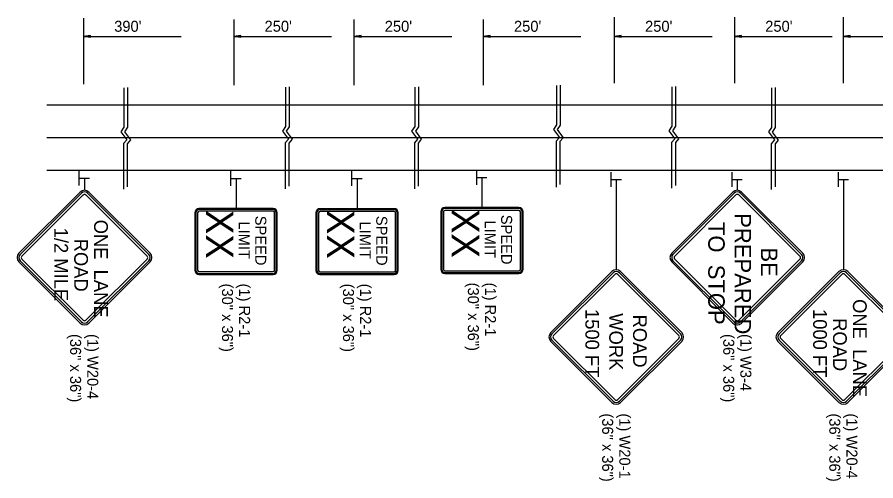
# Model space of a CAD drawing. Extents: x 1930579 to 1939784, y 596179 to 597522.
# Drawn here: x 1937482.9 to 1937952, y 596736 to 596989.5 of the extents above; entities that cross this region are included whole.
import ezdxf

# ---------------------------------------------------------------- set-up
doc = ezdxf.new("R2010")
doc.units = 0
for name, color, linetype in [('Default', 7, 'Continuous'), ('P_TC_Signs_Permanent', 7, 'Continuous'), ('P_TC_Signs_Temporary', 7, 'Continuous'), ('R_Annotation', 7, 'Continuous')]:
    doc.layers.add(name, color=color, linetype=linetype)

msp = doc.modelspace()

# ---------------------------------------------------------------- linework, layer by layer
at = {"layer": 'Default'}
for p, q in [((1937519.07, 596988.93), (1937519.07, 596952.91)), ((1937519.11, 596988.91), (1937519.11, 596952.89)), ((1937601.26, 596988.25), (1937601.26, 596952.22)), ((1937666.91, 596988.25), (1937666.91, 596952.22)), ((1937737.52, 596988.25), (1937737.52, 596952.22)), ((1937809.11, 596989.48), (1937809.11, 596953.45)), ((1937874.77, 596989.48), (1937874.77, 596953.45)), ((1937934.22, 596989.48), (1937934.22, 596953.45)), ((1937522.91, 596979.49), (1937519.07, 596978.92)), ((1937522.91, 596978.34), (1937519.07, 596978.92)), ((1937522.95, 596979.47), (1937519.11, 596978.9)), ((1937522.95, 596978.32), (1937519.11, 596978.9)), ((1937519.11, 596978.9), (1937572.51, 596978.9)), ((1937522.91, 596979.4), (1937519.71, 596978.92)), ((1937522.91, 596978.44), (1937519.71, 596978.92)), ((1937522.95, 596979.38), (1937519.75, 596978.9)), ((1937522.95, 596978.42), (1937519.75, 596978.9)), ((1937522.91, 596979.3), (1937520.37, 596978.92)), ((1937522.91, 596978.53), (1937520.37, 596978.92)), ((1937522.95, 596979.28), (1937520.41, 596978.9)), ((1937522.95, 596978.51), (1937520.41, 596978.9)), ((1937522.91, 596979.2), (1937521.01, 596978.92)), ((1937522.91, 596978.63), (1937521.01, 596978.92)), ((1937522.95, 596979.18), (1937521.05, 596978.9)), ((1937522.95, 596978.61), (1937521.05, 596978.9)), ((1937522.91, 596979.1), (1937521.66, 596978.92)), ((1937522.91, 596978.73), (1937521.66, 596978.92)), ((1937522.95, 596979.08), (1937521.7, 596978.9)), ((1937522.95, 596978.71), (1937521.7, 596978.9)), ((1937522.91, 596979.01), (1937522.3, 596978.92)), ((1937522.91, 596978.83), (1937522.3, 596978.92)), ((1937522.95, 596978.99), (1937522.34, 596978.9)), ((1937522.95, 596978.81), (1937522.34, 596978.9)), ((1937522.91, 596978.34), (1937522.91, 596979.49)), ((1937522.95, 596978.32), (1937522.95, 596979.47)), ((1937605.1, 596979.49), (1937601.26, 596978.92)), ((1937601.26, 596978.92), (1937654.66, 596978.92)), ((1937605.1, 596978.34), (1937601.26, 596978.92)), ((1937605.1, 596979.4), (1937601.9, 596978.92)), ((1937605.1, 596978.44), (1937601.9, 596978.92)), ((1937605.1, 596979.3), (1937602.56, 596978.92)), ((1937605.1, 596978.53), (1937602.56, 596978.92)), ((1937605.1, 596979.2), (1937603.2, 596978.92)), ((1937605.1, 596978.63), (1937603.2, 596978.92)), ((1937605.1, 596979.1), (1937603.85, 596978.92)), ((1937605.1, 596978.73), (1937603.85, 596978.92)), ((1937605.1, 596979.01), (1937604.49, 596978.92)), ((1937605.1, 596978.83), (1937604.49, 596978.92)), ((1937605.1, 596978.34), (1937605.1, 596979.49)), ((1937670.75, 596979.49), (1937666.91, 596978.92)), ((1937666.91, 596978.92), (1937720.31, 596978.92)), ((1937670.75, 596978.34), (1937666.91, 596978.92)), ((1937670.75, 596979.4), (1937667.55, 596978.92)), ((1937670.75, 596978.44), (1937667.55, 596978.92)), ((1937670.75, 596979.3), (1937668.21, 596978.92)), ((1937670.75, 596978.53), (1937668.21, 596978.92)), ((1937670.75, 596979.2), (1937668.85, 596978.92)), ((1937670.75, 596978.63), (1937668.85, 596978.92)), ((1937670.75, 596979.1), (1937669.5, 596978.92)), ((1937670.75, 596978.73), (1937669.5, 596978.92)), ((1937670.75, 596979.01), (1937670.14, 596978.92)), ((1937670.75, 596978.83), (1937670.14, 596978.92)), ((1937670.75, 596978.34), (1937670.75, 596979.49)), ((1937741.36, 596979.49), (1937737.52, 596978.92)), ((1937737.52, 596978.92), (1937790.92, 596978.92)), ((1937741.36, 596978.34), (1937737.52, 596978.92)), ((1937741.36, 596979.4), (1937738.16, 596978.92)), ((1937741.36, 596978.44), (1937738.16, 596978.92)), ((1937741.36, 596979.3), (1937738.82, 596978.92)), ((1937741.36, 596978.53), (1937738.82, 596978.92)), ((1937741.36, 596979.2), (1937739.46, 596978.92)), ((1937741.36, 596978.63), (1937739.46, 596978.92)), ((1937741.36, 596979.1), (1937740.11, 596978.92)), ((1937741.36, 596978.73), (1937740.11, 596978.92)), ((1937741.36, 596979.01), (1937740.75, 596978.92)), ((1937741.36, 596978.83), (1937740.75, 596978.92)), ((1937741.36, 596978.34), (1937741.36, 596979.49)), ((1937812.95, 596979.49), (1937809.11, 596978.92)), ((1937809.11, 596978.92), (1937862.52, 596978.92)), ((1937812.95, 596978.34), (1937809.11, 596978.92)), ((1937812.95, 596979.4), (1937809.76, 596978.92)), ((1937812.95, 596978.44), (1937809.76, 596978.92)), ((1937812.95, 596979.3), (1937810.42, 596978.92)), ((1937812.95, 596978.53), (1937810.42, 596978.92)), ((1937812.95, 596979.2), (1937811.05, 596978.92)), ((1937812.95, 596978.63), (1937811.05, 596978.92)), ((1937812.95, 596979.1), (1937811.7, 596978.92)), ((1937812.95, 596978.73), (1937811.7, 596978.92)), ((1937812.95, 596979.01), (1937812.35, 596978.92)), ((1937812.95, 596978.83), (1937812.35, 596978.92)), ((1937812.95, 596978.34), (1937812.95, 596979.49)), ((1937878.6, 596979.49), (1937874.77, 596978.92)), ((1937874.77, 596978.92), (1937928.17, 596978.92)), ((1937878.6, 596978.34), (1937874.77, 596978.92)), ((1937878.6, 596979.4), (1937875.41, 596978.92)), ((1937878.6, 596978.44), (1937875.41, 596978.92)), ((1937878.6, 596979.3), (1937876.07, 596978.92)), ((1937878.6, 596978.53), (1937876.07, 596978.92)), ((1937878.6, 596979.2), (1937876.71, 596978.92)), ((1937878.6, 596978.63), (1937876.71, 596978.92)), ((1937878.6, 596979.1), (1937877.36, 596978.92)), ((1937878.6, 596978.73), (1937877.36, 596978.92)), ((1937878.6, 596979.01), (1937878, 596978.92)), ((1937878.6, 596978.83), (1937878, 596978.92)), ((1937878.6, 596978.34), (1937878.6, 596979.49)), ((1937938.06, 596979.49), (1937934.22, 596978.92)), ((1937934.22, 596978.92), (1938033.98, 596978.92)), ((1937938.06, 596978.34), (1937934.22, 596978.92)), ((1937938.06, 596979.4), (1937934.86, 596978.92)), ((1937938.06, 596978.44), (1937934.86, 596978.92)), ((1937938.06, 596979.3), (1937935.52, 596978.92)), ((1937938.06, 596978.53), (1937935.52, 596978.92)), ((1937938.06, 596979.2), (1937936.16, 596978.92)), ((1937938.06, 596978.63), (1937936.16, 596978.92)), ((1937938.06, 596979.1), (1937936.81, 596978.92)), ((1937938.06, 596978.73), (1937936.81, 596978.92)), ((1937938.06, 596979.01), (1937937.45, 596978.92)), ((1937938.06, 596978.83), (1937937.45, 596978.92)), ((1937938.06, 596978.34), (1937938.06, 596979.49)), ((1937499.1, 596941.48), (1937601.26, 596941.48)), ((1937601.26, 596941.48), (1938703.26, 596941.48)), ((1937499.1, 596923.69), (1938703.26, 596923.69)), ((1937499.1, 596905.9), (1937601.26, 596905.9)), ((1937516.85, 596897.44), (1937516.85, 596905.45)), ((1937599.64, 596897.28), (1937599.64, 596905.28)), ((1937601.26, 596905.9), (1938703.26, 596905.9)), ((1937665.73, 596897.22), (1937665.73, 596905.22)), ((1937733.95, 596897.8), (1937733.95, 596905.8)), ((1937807.49, 596896.77), (1937807.49, 596904.77)), ((1937873.46, 596896.77), (1937873.46, 596904.77)), ((1937931.57, 596896.77), (1937931.57, 596904.77)), ((1937516.97, 596901.42), (1937522.43, 596901.42)), ((1937599.75, 596901.26), (1937605.22, 596901.26)), ((1937665.85, 596901.2), (1937671.32, 596901.2)), ((1937734.07, 596901.78), (1937739.54, 596901.78)), ((1937807.61, 596900.75), (1937813.07, 596900.75)), ((1937873.57, 596900.75), (1937879.04, 596900.75)), ((1937931.69, 596900.75), (1937937.15, 596900.75))]:
    msp.add_line(p, q, dxfattribs=at)
for points in [[(1937541.15, 596950.86), (1937541.15, 596929.33), (1937539.49, 596926.86), (1937542.73, 596922.43), (1937541.02, 596920.39), (1937541.02, 596895.36)], [(1937543.19, 596951.05), (1937543.19, 596929.25), (1937541.53, 596926.78), (1937544.77, 596922.35), (1937543.07, 596920.3), (1937543.06, 596896.8)], [(1937629.47, 596951.2), (1937629.47, 596929.67), (1937627.81, 596927.2), (1937631.05, 596922.77), (1937629.35, 596920.73), (1937629.34, 596895.7)], [(1937631.52, 596951.39), (1937631.52, 596929.59), (1937629.86, 596927.12), (1937633.09, 596922.69), (1937631.39, 596920.64), (1937631.39, 596897.14)], [(1937700.08, 596951.2), (1937700.08, 596929.67), (1937698.42, 596927.2), (1937701.66, 596922.77), (1937699.96, 596920.73), (1937699.95, 596895.7)], [(1937702.13, 596951.39), (1937702.13, 596929.59), (1937700.47, 596927.12), (1937703.7, 596922.69), (1937702, 596920.64), (1937702, 596897.14)], [(1937777.52, 596952.08), (1937777.52, 596930.56), (1937775.86, 596928.09), (1937779.1, 596923.66), (1937777.4, 596921.61), (1937777.39, 596896.59)], [(1937779.57, 596952.28), (1937779.57, 596930.47), (1937777.91, 596928), (1937781.14, 596923.57), (1937779.44, 596921.53), (1937779.44, 596898.03)], [(1937840.57, 596951.41), (1937840.57, 596929.89), (1937838.9, 596927.42), (1937842.14, 596922.99), (1937840.44, 596920.94), (1937840.43, 596895.92)], [(1937842.61, 596951.61), (1937842.61, 596929.8), (1937840.95, 596927.33), (1937844.19, 596922.9), (1937842.48, 596920.86), (1937842.48, 596897.36)], [(1937895.03, 596950.77), (1937895.03, 596929.24), (1937893.37, 596926.77), (1937896.6, 596922.34), (1937894.9, 596920.3), (1937894.89, 596895.27)], [(1937897.07, 596950.96), (1937897.07, 596929.16), (1937895.41, 596926.69), (1937898.65, 596922.26), (1937896.94, 596920.21), (1937896.94, 596896.71)]]:
    msp.add_lwpolyline(points, dxfattribs=at)
at = {"layer": 'P_TC_Signs_Permanent'}
for p, q in [((1937873.92, 596893.84), (1937840.51, 596860.43)), ((1937874.58, 596893.18), (1937841.17, 596859.77)), ((1937875.51, 596892.25), (1937842.1, 596858.84)), ((1937910.51, 596858.84), (1937877.1, 596892.25)), ((1937911.44, 596859.77), (1937878.03, 596893.18)), ((1937912.1, 596860.43), (1937878.69, 596893.84)), ((1937622.74, 596884.83), (1937582.24, 596884.83)), ((1937688.83, 596884.77), (1937648.33, 596884.77)), ((1937757.05, 596885.35), (1937716.55, 596885.35)), ((1937757.05, 596884.79), (1937716.55, 596884.79)), ((1937579.99, 596882.58), (1937579.99, 596851.08)), ((1937580.55, 596882.58), (1937580.55, 596851.08)), ((1937581.49, 596882.58), (1937581.49, 596851.08)), ((1937622.74, 596884.27), (1937582.24, 596884.27)), ((1937622.74, 596883.33), (1937582.24, 596883.33)), ((1937623.49, 596851.08), (1937623.49, 596882.58)), ((1937624.42, 596851.08), (1937624.42, 596882.58)), ((1937624.99, 596851.08), (1937624.99, 596882.58)), ((1937646.08, 596882.52), (1937646.08, 596851.02)), ((1937646.65, 596882.52), (1937646.65, 596851.02)), ((1937647.58, 596882.52), (1937647.58, 596851.02)), ((1937688.83, 596884.21), (1937648.33, 596884.21)), ((1937688.83, 596883.27), (1937648.33, 596883.27)), ((1937689.58, 596851.02), (1937689.58, 596882.52)), ((1937690.52, 596851.02), (1937690.52, 596882.52)), ((1937691.08, 596851.02), (1937691.08, 596882.52)), ((1937714.3, 596883.1), (1937714.3, 596851.6)), ((1937714.87, 596883.1), (1937714.87, 596851.6)), ((1937715.8, 596883.1), (1937715.8, 596851.6)), ((1937757.05, 596883.85), (1937716.55, 596883.85)), ((1937757.8, 596851.6), (1937757.8, 596883.1)), ((1937758.74, 596851.6), (1937758.74, 596883.1)), ((1937759.3, 596851.6), (1937759.3, 596883.1)), ((1937842.1, 596857.25), (1937875.51, 596823.84)), ((1937877.1, 596823.84), (1937910.51, 596857.25)), ((1937840.51, 596855.66), (1937873.92, 596822.25)), ((1937841.17, 596856.32), (1937874.58, 596822.91)), ((1937878.03, 596822.91), (1937911.44, 596856.32)), ((1937878.69, 596822.25), (1937912.1, 596855.66)), ((1937582.24, 596850.33), (1937622.74, 596850.33)), ((1937582.24, 596849.39), (1937622.74, 596849.39)), ((1937582.24, 596848.83), (1937622.74, 596848.83)), ((1937648.33, 596850.27), (1937688.83, 596850.27)), ((1937648.33, 596849.34), (1937688.83, 596849.34)), ((1937648.33, 596848.77), (1937688.83, 596848.77)), ((1937716.55, 596850.85), (1937757.05, 596850.85)), ((1937716.55, 596849.91), (1937757.05, 596849.91)), ((1937716.55, 596849.35), (1937757.05, 596849.35))]:
    msp.add_line(p, q, dxfattribs=at)
for centre, radius, start, end in [((1937876.31, 596891.45), 3.38, 45, 135), ((1937876.31, 596891.45), 2.44, 45, 135), ((1937876.31, 596891.45), 1.13, 45, 135), ((1937582.24, 596882.58), 2.25, 90, 180), ((1937622.74, 596882.58), 2.25, 360, 90), ((1937648.33, 596882.52), 2.25, 90, 180), ((1937688.83, 596882.52), 2.25, 360, 90), ((1937716.55, 596883.1), 2.25, 90, 180), ((1937716.55, 596883.1), 1.69, 90, 180), ((1937757.05, 596883.1), 2.25, 360, 90), ((1937757.05, 596883.1), 1.69, 360, 90), ((1937582.24, 596882.58), 1.69, 90, 180), ((1937582.24, 596882.58), 0.75, 90, 180), ((1937622.74, 596882.58), 1.69, 360, 90), ((1937622.74, 596882.58), 0.75, 360, 90), ((1937648.33, 596882.52), 1.69, 90, 180), ((1937648.33, 596882.52), 0.75, 90, 180), ((1937688.83, 596882.52), 1.69, 360, 90), ((1937688.83, 596882.52), 0.75, 360, 90), ((1937716.55, 596883.1), 0.75, 90, 180), ((1937757.05, 596883.1), 0.75, 360, 90), ((1937842.9, 596858.04), 3.38, 135, 225), ((1937842.9, 596858.04), 2.44, 135, 225), ((1937842.9, 596858.04), 1.13, 135, 225), ((1937909.72, 596858.04), 1.13, 315, 45), ((1937909.72, 596858.04), 2.44, 315, 45), ((1937909.72, 596858.04), 3.38, 315, 45), ((1937582.24, 596851.08), 2.25, 180, 270), ((1937582.24, 596851.08), 1.69, 180, 270), ((1937582.24, 596851.08), 0.75, 180, 270), ((1937622.74, 596851.08), 2.25, 270, 360), ((1937622.74, 596851.08), 1.69, 270, 360), ((1937622.74, 596851.08), 0.75, 270, 360), ((1937648.33, 596851.02), 2.25, 180, 270), ((1937648.33, 596851.02), 1.69, 180, 270), ((1937648.33, 596851.02), 0.75, 180, 270), ((1937688.83, 596851.02), 2.25, 270, 360), ((1937688.83, 596851.02), 1.69, 270, 360), ((1937688.83, 596851.02), 0.75, 270, 360), ((1937716.55, 596851.6), 2.25, 180, 270), ((1937716.55, 596851.6), 1.69, 180, 270), ((1937716.55, 596851.6), 0.75, 180, 270), ((1937757.05, 596851.6), 2.25, 270, 360), ((1937757.05, 596851.6), 1.69, 270, 360), ((1937757.05, 596851.6), 0.75, 270, 360), ((1937876.31, 596824.63), 1.13, 225, 315), ((1937876.31, 596824.63), 3.38, 225, 315), ((1937876.31, 596824.63), 2.44, 225, 315)]:
    msp.add_arc(centre, radius, start, end, dxfattribs=at)
at = {"layer": 'P_TC_Signs_Temporary'}
for p, q in [((1937483.9, 596860.43), (1937517.31, 596893.84)), ((1937484.56, 596859.77), (1937517.97, 596893.18)), ((1937485.49, 596858.84), (1937518.9, 596892.25)), ((1937520.49, 596892.25), (1937553.9, 596858.84)), ((1937521.42, 596893.18), (1937554.83, 596859.77)), ((1937522.08, 596893.84), (1937555.5, 596860.43)), ((1937518.9, 596823.84), (1937485.49, 596857.25)), ((1937553.9, 596857.25), (1937520.49, 596823.84)), ((1937517.31, 596822.25), (1937483.9, 596855.66)), ((1937517.97, 596822.91), (1937484.56, 596856.32)), ((1937554.83, 596856.32), (1937521.42, 596822.91)), ((1937555.5, 596855.66), (1937522.08, 596822.25)), ((1937774.37, 596816.99), (1937807.78, 596850.41)), ((1937775.03, 596816.33), (1937808.44, 596849.74)), ((1937775.96, 596815.4), (1937809.37, 596848.81)), ((1937810.96, 596848.81), (1937844.37, 596815.4)), ((1937811.89, 596849.74), (1937845.3, 596816.33)), ((1937812.55, 596850.41), (1937845.96, 596816.99)), ((1937898.45, 596816.99), (1937931.86, 596850.41)), ((1937899.11, 596816.33), (1937932.52, 596849.74)), ((1937900.04, 596815.4), (1937933.45, 596848.81)), ((1937935.04, 596848.81), (1937968.45, 596815.4)), ((1937935.97, 596849.74), (1937969.38, 596816.33)), ((1937936.63, 596850.41), (1937970.04, 596816.99)), ((1937807.78, 596778.81), (1937774.37, 596812.22)), ((1937808.44, 596779.47), (1937775.03, 596812.88)), ((1937809.37, 596780.4), (1937775.96, 596813.81)), ((1937844.37, 596813.81), (1937810.96, 596780.4)), ((1937845.3, 596812.88), (1937811.89, 596779.47)), ((1937845.96, 596812.22), (1937812.55, 596778.81)), ((1937931.86, 596778.81), (1937898.45, 596812.22)), ((1937932.52, 596779.47), (1937899.11, 596812.88)), ((1937933.45, 596780.4), (1937900.04, 596813.81)), ((1937968.45, 596813.81), (1937935.04, 596780.4)), ((1937969.38, 596812.88), (1937935.97, 596779.47)), ((1937970.04, 596812.22), (1937936.63, 596778.81))]:
    msp.add_line(p, q, dxfattribs=at)
for centre, radius, start, end in [((1937519.7, 596891.45), 3.37, 45, 135), ((1937519.7, 596891.45), 2.44, 45, 135), ((1937519.7, 596891.45), 1.12, 45, 135), ((1937486.29, 596858.04), 3.37, 135, 225), ((1937486.29, 596858.04), 2.44, 135, 225), ((1937486.29, 596858.04), 1.13, 135, 225), ((1937553.11, 596858.04), 1.13, 315, 45), ((1937553.11, 596858.04), 2.44, 315, 45), ((1937553.11, 596858.04), 3.37, 315, 45), ((1937810.17, 596848.02), 3.38, 45, 135), ((1937810.17, 596848.02), 2.44, 45, 135), ((1937810.17, 596848.02), 1.12, 45, 135), ((1937934.25, 596848.02), 3.38, 45, 135), ((1937934.25, 596848.02), 2.44, 45, 135), ((1937934.25, 596848.02), 1.12, 45, 135), ((1937519.7, 596824.63), 1.12, 225, 315), ((1937519.7, 596824.63), 3.38, 225, 315), ((1937519.7, 596824.63), 2.44, 225, 315), ((1937776.76, 596814.61), 3.38, 135, 225), ((1937776.76, 596814.61), 2.44, 135, 225), ((1937776.76, 596814.61), 1.13, 135, 225), ((1937843.58, 596814.61), 1.13, 315, 45), ((1937843.58, 596814.61), 2.44, 315, 45), ((1937843.58, 596814.61), 3.38, 315, 45), ((1937900.83, 596814.61), 3.38, 135, 225), ((1937900.83, 596814.61), 2.44, 135, 225), ((1937900.83, 596814.61), 1.13, 135, 225), ((1937810.17, 596781.2), 3.38, 225, 315), ((1937810.17, 596781.2), 2.44, 225, 315), ((1937810.17, 596781.2), 1.12, 225, 315), ((1937934.25, 596781.2), 3.38, 225, 315), ((1937934.25, 596781.2), 2.44, 225, 315), ((1937934.25, 596781.2), 1.12, 225, 315)]:
    msp.add_arc(centre, radius, start, end, dxfattribs=at)
at = {"layer": 'R_Annotation'}
for p, q in [((1937519.7, 596901.42), (1937519.7, 596894.83)), ((1937602.49, 596901.26), (1937602.49, 596884.83)), ((1937668.58, 596901.2), (1937668.58, 596884.77)), ((1937736.8, 596901.78), (1937736.8, 596885.35)), ((1937810.17, 596900.92), (1937810.17, 596851.39)), ((1937876.31, 596900.75), (1937876.31, 596894.83)), ((1937934.25, 596900.92), (1937934.25, 596851.39))]:
    msp.add_line(p, q, dxfattribs=at)

# ---------------------------------------------------------------- texts
at = {"layer": 'Default'}
for s, p in [("390'", (1937535.91, 596981.49)), ("250'", (1937618.06, 596981.51)), ("250'", (1937683.71, 596981.49)), ("250'", (1937754.32, 596981.49)), ("250'", (1937825.92, 596981.49)), ("250'", (1937891.57, 596981.49))]:
    msp.add_text(s, height=6, rotation=360, dxfattribs=at).set_placement(p)
at = {"layer": 'P_TC_Signs_Permanent'}
for s, height, p in [('XX', 15, (1937585.99, 596884.13)), ('SPEED', 6, (1937612.99, 596880.9)), ('XX', 15, (1937652.08, 596884.07)), ('SPEED', 6, (1937679.08, 596880.84)), ('XX', 15, (1937720.3, 596884.65)), ('SPEED', 6, (1937747.3, 596881.42)), ('LIMIT', 6, (1937603.99, 596877.81)), ('LIMIT', 6, (1937670.08, 596877.75)), ('LIMIT', 6, (1937738.3, 596878.33))]:
    msp.add_text(s, height=height, rotation=270, dxfattribs=at).set_placement(p)
at = {"layer": 'P_TC_Signs_Temporary'}
for s, height, p in [('PREPARED', 9, (1937874.83, 596882.28)), ('ONE  LANE', 7.5, (1937524.95, 596878.74)), ('TO  STOP', 9, (1937860.43, 596877.51)), ('1/2 MILE', 7.5, (1937503.2, 596874.36)), ('ROAD', 7.5, (1937514.07, 596868.35)), ('BE', 9, (1937889.23, 596863.59)), ('ONE  LANE', 7.5, (1937939.5, 596835.31)), ('1500 FT', 7.5, (1937793.33, 596829.9)), ('1000 FT', 7.5, (1937917.75, 596829.9)), ('WORK', 7.5, (1937806.36, 596827.6)), (' ROAD ', 7.5, (1937819.38, 596829.63)), ('ROAD', 7.5, (1937928.62, 596824.91))]:
    msp.add_text(s, height=height, rotation=270, dxfattribs=at).set_placement(p)
at = {"layer": 'R_Annotation'}
for s, height, p in [('(30" x 36")', 5.9996, (1937594.8, 596843.83)), ('(1) R2-1', 6, (1937604.17, 596843.83)), ('(30" x 36")', 5.9996, (1937660.9, 596843.77)), ('(1) R2-1', 6, (1937670.27, 596843.77)), ('(30" x 36")', 5.9996, (1937729.12, 596844.35)), ('(1) R2-1', 6, (1937738.48, 596844.35)), ('(36" x 36")', 5.9996, (1937511.84, 596816.26)), ('(1) W20-4', 6, (1937521.21, 596816.26)), ('(36" x 36")', 5.9996, (1937868.63, 596816.26)), ('(1) W3-4', 6, (1937877.99, 596816.26)), ('(36" x 36")', 5.9996, (1937802.49, 596772.82)), ('(1) W20-1', 6, (1937811.85, 596772.82)), ('(36" x 36")', 5.9996, (1937926.56, 596772.82)), ('(1) W20-4', 6, (1937935.93, 596772.82))]:
    msp.add_text(s, height=height, rotation=270, dxfattribs=at).set_placement(p)

doc.saveas('drawing.dxf')
